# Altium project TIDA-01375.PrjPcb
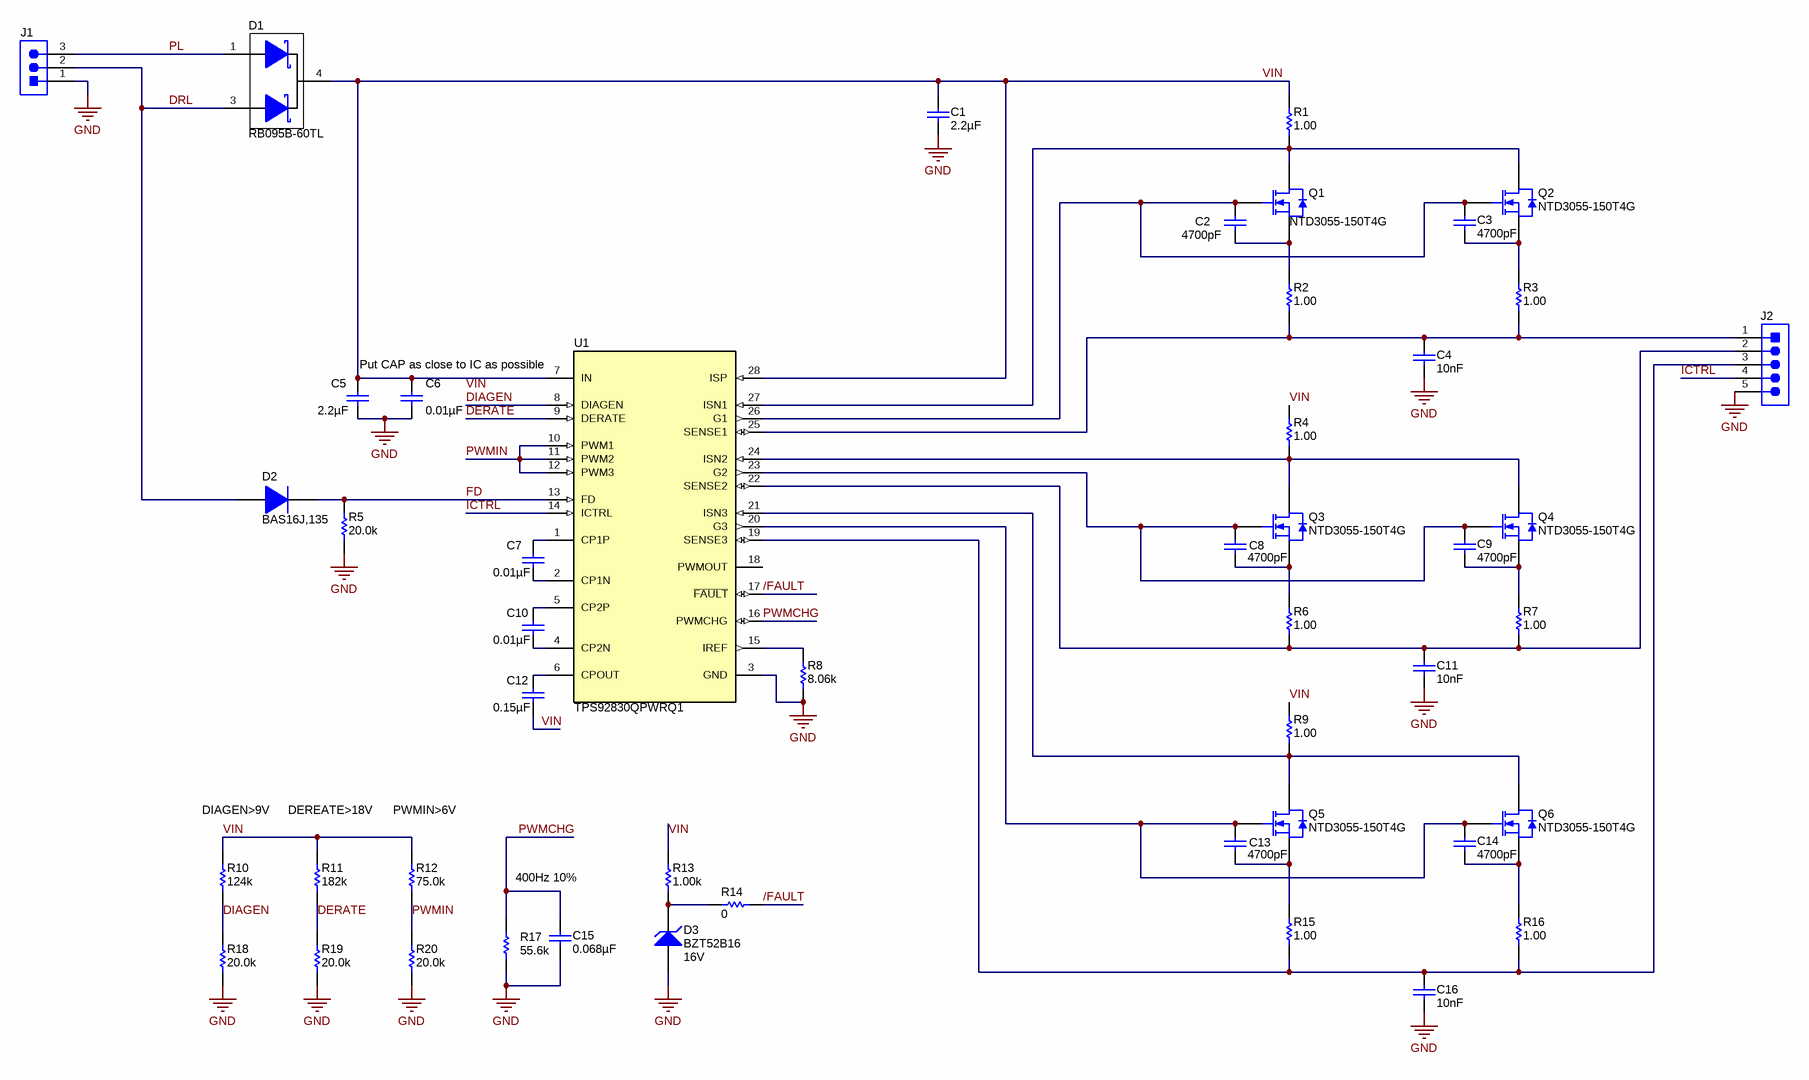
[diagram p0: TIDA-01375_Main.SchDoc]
CopyrightYear: 2017; EVM_Orderable: N/A; PCB_Layout: Anda Zhang; PCB_Rev: E1; PRJ_Customer: Public Release; PRJ_Engineer: Anda Zhang; PRJ_Number: TIDA-01375; PRJ_Title: DRL/position light reference design; SCH_Rev: E1; TechSupport: http://www.ti.com/support; TID: TIDA-01375
2 sheets, 53 parts. Net scope: global (net labels, ports and power ports of the same name join across sheets).
Board file: TIDA-01375_PCB.PcbDoc
Sheets:
  TIDA-01375_Main.SchDoc
  TIDA-01375_Hardware.SchDoc

## Sheet TIDA-01375_Main.SchDoc
size 431 x 279 mm; Date: Not shown in title block; ApprovedBy: Not shown in title block; CheckedBy: Not shown in title block; Author: Not shown in title block; CompanyName: Not shown in title block; Engineer: Not shown in title block; Organization: Not shown in title block; Address1: Not shown in title block; Address2: Not shown in title block; Address3: Not shown in title block; Address4: Not shown in title block; DocumentNumber: 1; Revision: Use project parameter SCH_Rev; SheetNumber: 2; SheetTotal: 3; PageSetup: Record=PageOptions¦CenterHorizontal=True¦CenterVertical=True¦PrintScale=1.00¦XCorrection=1.00¦YCorrection=1.00¦PrintKind=0¦BorderSize=5000000¦LeftOffset=0¦BottomOffset=0¦Orientation=2¦PaperLength=1000¦PaperWidth=1000¦Scale=100¦PaperSource=15¦PrintQuality=600¦MediaType=1¦DitherType=10¦PaperKind=Letter¦PrintScaleMode=1

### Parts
C1  ValueDisplayed: 2.2µF  [1206L]  (hidden comment: UMK316B7225KL-T)
C2  ValueDisplayed: 4700pF  [0603L]  (hidden comment: GRM188R71E472KA01D)
C3  ValueDisplayed: 4700pF  [0603L]  (hidden comment: GRM188R71E472KA01D)
C4  ValueDisplayed: 10nF  [0603L]  (hidden comment: 06031C103JAT2A)
C5  ValueDisplayed: 2.2µF  [1206L]  (hidden comment: UMK316B7225KL-T)
C6  ValueDisplayed: 0.01µF  [0603L]  (hidden comment: 06031C103JAT2A)
C7  ValueDisplayed: 0.01µF  [0402L]  (hidden comment: GCM155R71H103KA55D)
C8  ValueDisplayed: 4700pF  [0603L]  (hidden comment: GRM188R71E472KA01D)
C9  ValueDisplayed: 4700pF  [0603L]  (hidden comment: GRM188R71E472KA01D)
C10  ValueDisplayed: 0.01µF  [0402L]  (hidden comment: GCM155R71H103KA55D)
C11  ValueDisplayed: 10nF  [0603L]  (hidden comment: 06031C103JAT2A)
C12  ValueDisplayed: 0.15µF  [0805L]  (hidden comment: C0805C154K5RACTU)
C13  ValueDisplayed: 4700pF  [0603L]  (hidden comment: GRM188R71E472KA01D)
C14  ValueDisplayed: 4700pF  [0603L]  (hidden comment: GRM188R71E472KA01D)
C15  ValueDisplayed: 0.068µF  [0603L]  (hidden comment: GRM188R71C683KA01D)
C16  ValueDisplayed: 10nF  [0603L]  (hidden comment: 06031C103JAT2A)
D1  RB095B-60TL  [DPAK]
D2  BAS16J,135  [SOD-323F]
D3  BZT52B16  value 16V  [SOD-123]
J1  IPL1-103-01-F-S-RA-K  [Samtec_IPL1-103-01-x-S-RA-K]  (value not drawn)
J2  IPL1-105-01-L-S-RA-K  [Samtec_IPL1-105-01-x-S-RA-K]  (value not drawn)
Q1  NTD3055-150T4G  [DPAK]
Q2  NTD3055-150T4G  [DPAK]
Q3  NTD3055-150T4G  [DPAK]
Q4  NTD3055-150T4G  [DPAK]
Q5  NTD3055-150T4G  [DPAK]
Q6  NTD3055-150T4G  [DPAK]
R1  ValueDisplayed: 1.00  [1206L]  (hidden comment: CSR1206FK1R00)
R2  ValueDisplayed: 1.00  [1206L]  (hidden comment: CSR1206FK1R00)
R3  ValueDisplayed: 1.00  [1206L]  (hidden comment: CSR1206FK1R00)
R4  ValueDisplayed: 1.00  [1206L]  (hidden comment: CSR1206FK1R00)
R5  ValueDisplayed: 20.0k  [0603L]  (hidden comment: CRCW060320K0FKEA)
R6  ValueDisplayed: 1.00  [1206L]  (hidden comment: CSR1206FK1R00)
R7  ValueDisplayed: 1.00  [1206L]  (hidden comment: CSR1206FK1R00)
R8  ValueDisplayed: 8.06k  [0603L]  (hidden comment: RT0603BRD078K06L)
R9  ValueDisplayed: 1.00  [1206L]  (hidden comment: CSR1206FK1R00)
R10  ValueDisplayed: 124k  [0603L]  (hidden comment: CRCW0603124KFKEA)
R11  ValueDisplayed: 182k  [0603L]  (hidden comment: CRCW0603182KFKEA)
R12  ValueDisplayed: 75.0k  [0603L]  (hidden comment: CRCW060375K0FKEA)
R13  ValueDisplayed: 1.00k  [0603L]  (hidden comment: CRCW06031K00FKEA)
R14  ValueDisplayed: 0  [0603L]  (hidden comment: DNP)
R15  ValueDisplayed: 1.00  [1206L]  (hidden comment: CSR1206FK1R00)
R16  ValueDisplayed: 1.00  [1206L]  (hidden comment: CSR1206FK1R00)
R17  ValueDisplayed: 55.6k  [0603L]  (hidden comment: RT0603DRE0755K6L)
R18  ValueDisplayed: 20.0k  [0603L]  (hidden comment: CRCW060320K0FKEA)
R19  ValueDisplayed: 20.0k  [0603L]  (hidden comment: CRCW060320K0FKEA)
R20  ValueDisplayed: 20.0k  [0603L]  (hidden comment: CRCW060320K0FKEA)
U1  TPS92830QPWRQ1  [PW0028A_N]

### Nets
GND: C1.2 C4.2 C5.2 C6.2 C11.2 C15.2 C16.2 D3.2(A) J1.1 J2.5 R5.1 R8.1 R17.1 R18.1 R19.1 R20.1 U1.3(GND)
/FAULT: R14.2 U1.17(~{FAULT})
DERATE: R11.1 R19.2 U1.9(DERATE)
DIAGEN: R10.1 R18.2 U1.8(DIAGEN)
DRL: D1.3(A) D2.2(A) J1.2
FD: D2.1(K) R5.2 U1.13(FD)
ICTRL: J2.4 U1.14(ICTRL)
PL: D1.1(A) J1.3
PWMCHG: C15.1 R17.2 U1.16(PWMCHG)
PWMIN: R12.1 R20.2 U1.10(PWM1) U1.11(PWM2) U1.12(PWM3)
VIN: C1.1 C5.1 C6.1 C12.2 D1.4(K) R1.2 R4.2 R9.2 R10.2 R11.2 R12.2 R13.2 U1.7(IN) U1.28(ISP)
NetC2_1: C2.1 C3.2 Q1.1(G) Q2.1(G) U1.26(G1)
NetC2_2: C2.2 Q1.3(S) R2.2
NetC3_1: C3.1 Q2.3(S) R3.2
NetC4_1: C4.1 J2.1 R2.1 R3.1 U1.25(SENSE1)
NetC7_1: C7.1 U1.1(CP1P)
NetC7_2: C7.2 U1.2(CP1N)
NetC8_1: C8.1 C9.2 Q3.1(G) Q4.1(G) U1.23(G2)
NetC8_2: C8.2 Q3.3(S) R6.2
NetC9_1: C9.1 Q4.3(S) R7.2
NetC10_1: C10.1 U1.5(CP2P)
NetC10_2: C10.2 U1.4(CP2N)
NetC11_1: C11.1 J2.2 R6.1 R7.1 U1.22(SENSE2)
NetC12_1: C12.1 U1.6(CPOUT)
NetC13_1: C13.1 C14.2 Q5.1(G) Q6.1(G) U1.20(G3)
NetC13_2: C13.2 Q5.3(S) R15.2
NetC14_1: C14.1 Q6.3(S) R16.2
NetC16_1: C16.1 J2.3 R15.1 R16.1 U1.19(SENSE3)
NetD3_1: D3.1(K) R13.1 R14.1
NetQ1_4: Q1.4(D) Q2.4(D) R1.1 U1.27(ISN1)
NetQ3_4: Q3.4(D) Q4.4(D) R4.1 U1.24(ISN2)
NetQ5_4: Q5.4(D) Q6.4(D) R9.1 U1.21(ISN3)
NetR8_2: R8.2 U1.15(IREF)

Not connected (* = marked no-connect by the designer): U1 18(PWMOUT)

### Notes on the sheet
- Put CAP as close to IC as possible
- DIAGEN>9V
- DEREATE>18V
- (near R12) PWMIN>6V
- 400Hz 10%
- Labels drawn without touching a wire or pin: VIN

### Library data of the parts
C1 C5 = UMK316B7225KL-T: CAP, CERM, 2.2 µF, 50 V, +/- 10%, X7R, 1206; Manufacturer: Taiyo Yuden; Polarized: N; CompType: Capacitor; Value: 2.2uF; U/M: EA; Cap_F: 0.0000022; Tolerance_%: 10; Value1: Unknown; VDC_V: 50; Value2: 50V; TaMin_C: -55; TaMax_C: 125; Cap_Case: 1206; AEC Category: Q200
C2 C3 C8 C9 C13 C14 = GRM188R71E472KA01D: CAP, CERM, 4700 pF, 25 V, +/- 10%, X7R, 0603; Manufacturer: MuRata; Polarized: N; CompType: Capacitor; Value: 4700pF; U/M: EA; Cap_F: 0.0000000047; Tolerance_%: 10; Value1: Unknown; VDC_V: 25; Value2: 25V; TaMin_C: -55; TaMax_C: 125; Cap_Case: 0603; SizeArea_mm2: 1.28; SizeAreaWB_mm2: 4.68; SizeX_mm: 1.6; SizeY_mm: 0.8; SizeZ_mm: 1; AEC Category: Q200
C4 C6 C11 C16 = 06031C103JAT2A: CAP, CERM, 0.01 µF, 100 V, +/- 5%, X7R, 0603; Manufacturer: AVX; Polarized: N; CompType: Capacitor; Value: 0.01uF; U/M: EA; Cap_F: 0.00000001; Tolerance_%: 5; ESR_ohm: 0.098; Value1: 0.098 ohm; VDC_V: 100; Value2: 100V; TaMin_C: -55; TaMax_C: 125; Cap_Case: 0603; AEC Category: Q200
C7 C10 = GCM155R71H103KA55D: CAP, CERM, 0.01 µF, 50 V, +/- 10%, C0G/NP0, 0402; Manufacturer: MuRata; Polarized: N; CompType: Capacitor; Value: 0.01uF; U/M: EA; Cap_F: 0.00000001; Tolerance_%: 10; Value1: Unknown; VDC_V: 50; Value2: 50V; TaMin_C: -55; TaMax_C: 125; Cap_Case: 0402; SizeArea_mm2: 0.5; SizeAreaWB_mm2: 3; SizeX_mm: 1; SizeZ_mm: 0.6; AEC Category: Q200
C12 = C0805C154K5RACTU: CAP, CERM, 0.15 µF, 50 V, +/- 10%, X7R, 0805; Manufacturer: Kemet; Polarized: N; CompType: Capacitor; Value: 0.15uF; U/M: EA; Cap_F: 0.00000015; Tolerance_%: 10; ESR_ohm: 0.054; Value1: 0.054 ohm; VDC_V: 50; Value2: 50V; IRMS_A: 2.09; TaMin_C: -55; TaMax_C: 125; Cap_Case: 0805; AEC Category: Q200
C15 = GRM188R71C683KA01D: CAP, CERM, 0.068 µF, 16 V, +/- 10%, X7R, 0603; Manufacturer: MuRata; Polarized: N; CompType: Capacitor; Value: 0.068uF; U/M: EA; Cap_F: 0.000000068; Tolerance_%: 10; Value1: Unknown; VDC_V: 16; Value2: 16V; TaMin_C: -55; TaMax_C: 125; Cap_Case: 0603; SizeArea_mm2: 1.28; SizeAreaWB_mm2: 4.68; SizeX_mm: 1.6; SizeY_mm: 0.8; SizeZ_mm: 1; AEC Category: Q200
D1 = RB095B-60TL: Diode, Schottky, 60 V, 3 A, DPAK; Manufacturer: Rohm; U/M: EA; Vf_V: 0.58; Value: 60V; Value1: 3A; Value2: 0.58V; Io_A: 3; Vr_V: 60; TJmax_C: 150; SizeAreaWB_mm2: 101.7114; SizeArea_mm2: 64.8114; SizeX_mm: 9.91; SizeY_mm: 6.54; SizeZ_mm: 2.29; AEC Category: Q101
D2 = BAS16J,135: Diode, Switching, 100 V, 0.25 A, SOD-323F; Manufacturer: NXP Semiconductor; U/M: EA; Value: 100V; Value1: 0.25A; Io_A: 0.25; Vr_V: 100; TJmax_C: 150; SizeAreaWB_mm2: 7.875; SizeArea_mm2: 3.125; SizeX_mm: 2.5; SizeY_mm: 1.25; SizeZ_mm: 0.8; AEC Category: Q101
D3 = BZT52B16-HE3-08: Diode, Zener, 16 V, 410 mW, AEC-Q101, SOD-123; Manufacturer: Vishay-Semiconductor; SymbolCreator: a0412235; U/M: EA; Power_W: 0.41; Vz_V: 16; Value1: 0.41W; RJA_CperW: 300; SizeAreaWB_mm2: 13.095; SizeArea_mm2: 6.545; SizeX_mm: 3.85; SizeY_mm: 1.7; SizeZ_mm: 1.35; AEC Category: Q101; AEC Qualified: Y
J1 = IPL1-103-01-F-S-RA-K: Header(Shrouded), 2.54mm, 3x1, Gold, R/A, TH; Manufacturer: Samtec; SymbolCreator: a0799628; Pitch_mm: 2.54; Gender: Male; Shrouded: Y; Row_Count: 1; Current_A: 3.8; Voltage_V: 954
J2 = IPL1-105-01-L-S-RA-K: Header(Shrouded), 2.54mm, 5x1, Gold, R/A, TH; Manufacturer: Samtec; SymbolCreator: a0412235; Pitch_mm: 2.54; Gender: Male; Shrouded: Y; Row_Count: 1; Current_A: 3.8; Voltage_V: 954
Q1-Q6 = NTD3055-150T4G: MOSFET, N-CH, 60 V, 9 A, AEC-Q101, DPAK; Manufacturer: ON Semiconductor; Alternate Manufacturer: None; U/M: EA; ChType: N; Value: 60V; VdsMax_V: 60; Value1: ? ohm; Value2: 7.1 nC; QgTyp_nC: 7.1; Vgs_V: 20; IdsMax_A: 9; SizeAreaWB_mm2: 101.7114; SizeArea_mm2: 64.8114; SizeX_mm: 9.91; SizeY_mm: 6.54; SizeZ_mm: 2.29; AEC Category: Q101; AEC Qualified: Y
R1-R4 R6 R7 R9 R15 R16 = CSR1206FK1R00: RES, 1.00, 1%, 0.5 W, 1206; Manufacturer: Stackpole Electronics Inc; CompType: Resistor; Value: 1.00; Res_ohm: 1; Value_Code: 1R00; Power_W: 0.5; Value2: 0.5W; TempCo: 100 ppm/C; SizeArea_mm2: 5.12; SizeX_mm: 3.2; SizeY_mm: 1.6; SizeZ_mm: 1.35; EIA_Code: E96; U/M: EA; AEC Category: Q200
R5 R18-R20 = CRCW060320K0FKEA: RES, 20.0 k, 1%, 0.1 W, 0603; Manufacturer: Vishay-Dale; CompType: Resistor; Value: 20.0k; Res_ohm: 20000; Value_Code: 20k0; Tolerance_%: 1; Power_W: 0.1; Value2: 0.1W; VDC_V: 75; TempCo: 100 ppm/C; EIA_Code: E96; U/M: EA; AEC Category: Q200
R8 = RT0603BRD078K06L: RES, 8.06 k, 0.1%, 0.1 W, 0603; Manufacturer: Yageo America; CompType: Resistor; Value: 8.06k; Res_ohm: 8060; Value_Code: 8k06; Tolerance_%: 0.1; Value2: 0.1W; VDC_V: 75; TempCo: 25 ppm/C; EIA_Code: E192; U/M: EA; AEC Category: Q200
R10 = CMP-0022026-3: RES, 124 k, 1%, 0.1 W, 0603; Manufacturer: Vishay-Dale; Power_W: 100mW; TempCo: 100 ppm/C; U/M: EA; Value: 124k; EIA_Code: E96; SizeX_mm: 1.6; SizeY_mm: 0.8; SizeZ_mm: 1; Value2: 0.1W; SizeArea_mm2: 1.28; CompType: Resistor; VDC_V: 75V; AEC Category: Q200
R11 = CMP-0022093-3: RES, 182 k, 1%, 0.1 W, 0603; Manufacturer: Vishay-Dale; Power_W: 100mW; TempCo: 100 ppm/C; U/M: EA; Value: 182k; EIA_Code: E96; SizeX_mm: 1.6; SizeY_mm: 0.8; SizeZ_mm: 1; Value2: 0.1W; SizeArea_mm2: 1.28; CompType: Resistor; VDC_V: 75V; AEC Category: Q200
R12 = CMP-0022589-3: RES, 75.0 k, 1%, 0.1 W, 0603; Manufacturer: Vishay-Dale; Power_W: 100mW; TempCo: 100 ppm/C; Value_Code: 75k0; U/M: EA; Value: 75.0k; EIA_Code: E96; Res_ohm: 75k; SizeX_mm: 1.6; SizeY_mm: 0.8; SizeZ_mm: 1; Value2: 0.1W; SizeArea_mm2: 1.28; CompType: Resistor; VDC_V: 75V; AEC Category: Q200
R13 = CRCW06031K00FKEA: RES, 1.00 k, 1%, 0.1 W, 0603; Manufacturer: Vishay-Dale; CompType: Resistor; Value: 1.00k; Res_ohm: 1000; Value_Code: 1k00; Tolerance_%: 1; Power_W: 0.1; Value2: 0.1W; VDC_V: 75; TempCo: 100 ppm/C; EIA_Code: E96; U/M: EA; AEC Category: Q200
R14 = CRCW06030000Z0EA: RES, 0, 5%, 0.1 W, 0603; Manufacturer: Vishay-Dale; CompType: Resistor; Value: 0; Value_Code: 0000; Tolerance_%: 5; Power_W: 0.1; Value2: 0.1W; VDC_V: 75; TempCo: 200 ppm/C; EIA_Code: E24; U/M: EA; AEC Category: Q200
R17 = RT0603DRE0755K6L: RES, 55.6 k, 0.5%, 0.1 W, 0603; Manufacturer: Yageo America; CompType: Resistor; Value: 55.6k; Res_ohm: 55600; Value_Code: 55k6; Tolerance_%: 0.5; Power_W: 0.1; Value2: 0.1W; VDC_V: 75; TempCo: 50 ppm/C; SizeArea_mm2: 1.28; SizeX_mm: 1.6; SizeY_mm: 0.8; SizeZ_mm: 1; EIA_Code: E192; U/M: EA; AEC Category: Q200
U1 = TPS92830QPWRQ1: 3-CH High Current Linear LED Controller with Diagnostics and One-Fail-All-Fail Fault Bus, PW0028A; Manufacturer: Texas Instruments; SymbolCreator: Altium; SizeX_mm: 6.4; SizeY_mm: 9.7; SizeZ_mm: 1.2; CompType: IC; U/M: EA

## Sheet TIDA-01375_Hardware.SchDoc
size 431 x 279 mm; Date: Not shown in title block; ApprovedBy: Not shown in title block; CheckedBy: Not shown in title block; Author: Not shown in title block; CompanyName: Not shown in title block; Engineer: Not shown in title block; Organization: Not shown in title block; Address1: Not shown in title block; Address2: Not shown in title block; Address3: Not shown in title block; Address4: Not shown in title block; DocumentNumber: 1; Revision: Use project parameter SCH_Rev; SheetNumber: 3; SheetTotal: 3; PageSetup: Record=PageOptions¦CenterHorizontal=True¦CenterVertical=True¦PrintScale=1.00¦XCorrection=1.00¦YCorrection=1.00¦PrintKind=0¦BorderSize=5000000¦LeftOffset=0¦BottomOffset=0¦Orientation=2¦PaperLength=1000¦PaperWidth=1000¦Scale=100¦PaperSource=15¦PrintQuality=600¦MediaType=1¦DitherType=10¦PaperKind=Letter¦PrintScaleMode=1
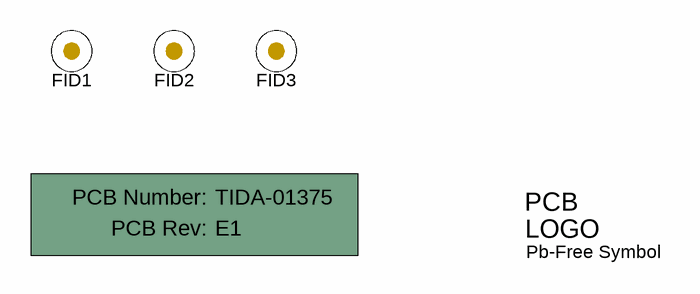
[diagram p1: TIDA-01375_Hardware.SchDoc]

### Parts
!PCB1  Printed Circuit Board  (value not drawn)  (mechanical)
FID1  Fiducial  [Fiducial10-20]  (value not drawn)
FID2  Fiducial  [Fiducial10-20]  (value not drawn)
FID3  Fiducial  [Fiducial10-20]  (value not drawn)
Logo2  Pb-Free Symbol  [Pb-Free_Overlay_Small]  (no BOM)

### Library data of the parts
!PCB1 = PCB: Manufacturer: Any; PartNumber: TIDA-01375; SymbolCreator: a0412235
FID1-FID3 = Fiducial: Fiducial mark.  There is nothing to buy or mount.; SymbolCreator: codlsc
Logo2 = Pb-Free: SymbolCreator: a0412235

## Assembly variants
001: not fitted FID1 FID2 FID3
